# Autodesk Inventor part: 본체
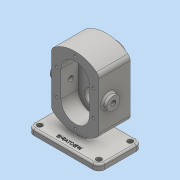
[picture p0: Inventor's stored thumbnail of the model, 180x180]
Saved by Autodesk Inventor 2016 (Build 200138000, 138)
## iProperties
Created: 2019-03
Part Number: 본체
Material: Generic
Document SubType Name: Modeling
Designer: 2-PC10
Density: 1 g/cm^3
Appearance: Default
Author: 2-PC10
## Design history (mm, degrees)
sketch "스케치1"
  geometry: L1 (-60, -36.5)-(60, -36.5); L2 (60, -36.5)-(60, 36.5); L3 (60, 36.5)-(-60, 36.5); L4 (-60, 36.5)-(-60, -36.5); L5 (-60, -36.5)-(60, 36.5); L6 (60, -36.5)-(-60, 36.5); 1 further point
  constraints: 12 end point, 2 midpoint, 2 parallel, 1 horizontal, 1 perpendicular
  dimensions: "d0" = 120 distance of L2.end L3.end; "d1" = 73 distance of L3.end L1.start
extrude "돌출1" new body sketch "스케치1" distance "d2" = 10; taper "d3" = 0 deg
node "작업 평면1"
sketch "스케치2"
  geometry: L1 (120, 10)-(120, 0) reference; L2 (120, 0)-(0, 0) reference; L3 (0, 0)-(0, 10) reference; L4 (0, 10)-(120, 10) reference; L5 (20, 122.721)-(20, 33.279); L6 (100, 122.721)-(100, 33.279); L7 (20, 78)-(100, 78); A1 r 60 centre (60, 78) between (20, 33.279) and (100, 33.279); A2 r 60 centre (60, 78) between (100, 122.721) and (20, 122.721); 2 further points
  constraints: 6 end point, 5 point on circle, 3 midpoint, 2 centre point, 2 vertical, 1 tangent
  dimensions: "d5" = 40 distance from line of point (60, 0) L5; "d6" = 40 distance from line of L6 point (60, 0); "d7" = 78 distance between parallel lines of L2 L7; "d9" = 138 distance of point (60, 0) point (60, 138); "d10" = 60 radius of A2
extrude "돌출2" join sketch "스케치2" distance "d11" = 53; taper "d12" = 0 deg
sketch "스케치3"
  geometry: L1 (120, 10)-(120, 0) reference; L2 (120, 0)-(0, 0) reference; L3 (0, 0)-(0, 10) reference; L4 (0, 10)-(120, 10) reference; L5 (20, 33.279)-(20, 122.721) reference; L6 (100, 122.721)-(100, 33.279) reference; L7 (36, 100)-(36, 56); L8 (84, 100)-(84, 56); A1 r 60 centre (60, 78) between (20, 33.279) and (100, 33.279) reference; A2 r 60 centre (60, 78) between (100, 122.721) and (20, 122.721) reference; A3 r 24 centre (60, 100) between (84, 100) and (36, 100); A4 r 24 centre (60, 56) between (36, 56) and (84, 56); 1 further point
  constraints: 4 end point, 4 point on circle, 2 centre point, 2 tangent, 2 vertical, 1 equal radius
  dimensions: "d13" = 24 distance from line of L7 A1.centre; "d14" = 24 distance from line of L8 A1.centre; "d18" = 24 radius of A3; "d19" = 100 distance from line of L8.start L2; "d20" = 56 distance from line of L8.end L2
extrude "돌출3" cut sketch "스케치3" distance "d21" = 29; taper "d22" = 0 deg
sketch "스케치4"
  geometry: L1 (12.5, 100)-(12.5, 112.5); L2 (12.5, 112.5)-(27.5, 112.5); L3 (27.5, 112.5)-(27.5, 108.5); L4 (27.5, 108.5)-(36.5, 108.5); L5 (36.5, 108.5)-(36.5, 100); L6 (36.5, 100)-(12.5, 100); L7 (-16.5, 138)-(36.5, 138) reference; L8 (36.5, 138)-(36.5, 18) reference; L9 (36.5, 18)-(-16.5, 18) reference; L10 (-16.5, 18)-(-16.5, 32) reference; L11 (-16.5, 32)-(12.5, 32) reference; L12 (12.5, 32)-(12.5, 124) reference; L13 (12.5, 124)-(-16.5, 124) reference; L14 (-16.5, 124)-(-16.5, 138) reference; L15 (-36.5, 0)-(-36.5, 10) reference; L16 (-36.5, 10)-(36.5, 10) reference; L17 (36.5, 10)-(36.5, 0) reference; L18 (36.5, 0)-(-36.5, 0) reference; L19 (-16.5, 100)-(12.5, 100) reference; 1 further point
  constraints: 12 end point, 3 perpendicular, 2 collinear, 2 vertical, 1 parallel, 1 point on line
  dimensions: "d23" = 15 distance between parallel lines of L3 L1; "d24" = 17 diameter of L4 L6; "d25" = 25 diameter of L2 L6
revolve "회전1" sketch "스케치4" stored, may be unused: angle "d26" = 90 deg
sketch "스케치5"
  geometry: L1 (12.5, 56)-(12.5, 68.5); L2 (27.5, 68.5)-(27.5, 56); L3 (27.5, 56)-(12.5, 56); L4 (-16.5, 56)-(12.5, 56) reference; L5 (36.5, 18)-(-16.5, 18) reference; L6 (-16.5, 18)-(-16.5, 32) reference; L7 (-16.5, 32)-(12.5, 32) reference; L8 (12.5, 32)-(12.5, 87.5) reference; L9 (12.5, 87.5)-(27.5, 87.5) reference; L10 (27.5, 87.5)-(27.5, 91.5) reference; L11 (27.5, 91.5)-(36.5, 91.5) reference; L12 (36.5, 91.5)-(36.5, 18) reference; L13 (-16.5, 138)-(36.5, 138) reference; L14 (36.5, 138)-(36.5, 108.5) reference; L15 (36.5, 108.5)-(27.5, 108.5) reference; L16 (27.5, 108.5)-(27.5, 112.5) reference; L17 (27.5, 112.5)-(12.5, 112.5) reference; L18 (12.5, 112.5)-(12.5, 124) reference; L19 (12.5, 124)-(-16.5, 124) reference; L20 (-16.5, 124)-(-16.5, 138) reference; L21 (-36.5, 0)-(-36.5, 10) reference; L22 (-36.5, 10)-(36.5, 10) reference; L23 (36.5, 10)-(36.5, 0) reference; L24 (36.5, 0)-(-36.5, 0) reference; L25 (12.5, 68.5)-(27.5, 68.5); 1 further point
  constraints: 8 end point, 1 collinear, 1 horizontal, 1 perpendicular, 1 point on line, 1 vertical
  dimensions: "d29" = 15 distance between parallel lines of L2 L1; "d30" = 25 diameter of L25 L3
revolve "회전2" sketch "스케치5" stored, may be unused: angle "d31" = 90 deg
node "작업 평면2"
sketch "스케치7"
  geometry: L1 (-60, 0)-(60, 0) reference; C1 r 19 at (0, 100); 2 further points
  constraints: 1 centre point, 1 midpoint, 1 vertical alignment
  dimensions: "d36" = 38 diameter of C1; "d37" = 100 distance of point (0, 0) C1.centre
extrude "돌출5" join sketch "스케치7" distance "d38" = 17; taper "d39" = 0 deg
hole "구멍1" diameter "d42" = 28; stored, may be unused: countersink angle "d46" = 90 deg, drill point angle "d48" = 0 deg; dims "d43" = 6, "d44" = 4, "d45" = 2, "d47" = 7.3, "d49" = 10, "d50" = 10
hole "구멍2" diameter "d53" = 17; stored, may be unused: countersink angle "d57" = 90 deg, drill point angle "d59" = 118 deg; dims "d51" = 10, "d52" = 10, "d54" = 6, "d55" = 4, "d56" = 2, "d58" = 7.3
sketch "스케치8"
  geometry: L1 (122.721, -20)-(122.721, 53) reference; L2 (0, 0)-(0, 53) reference; L3 (0, 53)-(89.443, 53) reference; L4 (89.443, 53)-(89.443, 0) reference; L5 (89.443, 0)-(0, 0) reference; L6 (122.721, -20)-(112.721, -20) reference; L7 (112.721, -20)-(112.721, 53) reference; L8 (112.721, 53)-(122.721, 53) reference; L9 (122.721, 53)-(122.721, -20) reference; C1 r 11 at (44.721, 16.5); 3 further points
  constraints: 2 midpoint, 1 centre point, 1 horizontal alignment, 1 vertical alignment
  dimensions: "d60" = 22 diameter of C1
extrude "돌출6" join sketch "스케치8" distance "d61" = 8; taper "d62" = 0 deg
fillet "모깎기1" dims "d63" = 10
hole "구멍3" diameter "d66" = 9; stored, may be unused: countersink angle "d70" = 90 deg, drill point angle "d72" = 118 deg; dims "d64" = 10, "d65" = 10, "d67" = 6, "d68" = 4, "d69" = 2, "d71" = 7.3
hole "구멍4" diameter "d75" = 9; stored, may be unused: countersink angle "d79" = 90 deg, drill point angle "d81" = 118 deg; dims "d73" = 10, "d74" = 10, "d76" = 6, "d77" = 4, "d78" = 2, "d80" = 7.3
hole "구멍5" diameter "d84" = 9; stored, may be unused: countersink angle "d88" = 90 deg, drill point angle "d90" = 118 deg; dims "d82" = 10, "d83" = 10, "d85" = 6, "d86" = 4, "d87" = 2, "d89" = 7.3
hole "구멍6" diameter "d93" = 9; stored, may be unused: countersink angle "d97" = 90 deg, drill point angle "d99" = 118 deg; dims "d91" = 10, "d92" = 10, "d94" = 6, "d95" = 4, "d96" = 2, "d98" = 7.3
sketch "스케치9"
  geometry: L1 (-25, -22.5)-(25, -22.5); L2 (25, -22.5)-(25, -30.5); L3 (25, -30.5)-(-25, -30.5); L4 (-25, -30.5)-(-25, -22.5); L5 (-25, -26.5)-(25, -26.5); L6 (0, -22.5)-(0, -30.5); L7 (-60, 26.5)-(-60, -26.5) reference; L8 (-50, -36.5)-(50, -36.5) reference; 1 further point
  constraints: 4 end point, 4 midpoint, 2 other
  dimensions: "d100" = 8 distance of L6.start L6.end; "d101" = 50 distance of L5.start L5.end; "d102" = 60 distance between parallel lines of L6 L7; "d103" = 10 distance between parallel lines of L5 L8
feature "엠보싱1" sketch "스케치9" dims "d104" = 0.5, "d105" = 0
sketch "스케치10"
  geometry: L1 (-6, -6.5)-(6, -6.5); L2 (6, -6.5)-(6, 36.5); L3 (6, 36.5)-(-6, 36.5); L4 (-6, 36.5)-(-6, -6.5); L5 (18.989, -26.503)-(17.659, -26.503) reference; L6 (17.659, -26.503)-(17.659, -26.123) reference; L7 (17.659, -26.123)-(18.989, -26.123) reference; L8 (18.989, -26.123)-(18.989, -23.545) reference; L9 (18.989, -23.545)-(19.315, -23.545) reference; L10 (19.45, -23.81)-(19.45, -29.482) reference; L11 (19.45, -29.482)-(18.989, -29.482) reference; L12 (18.989, -29.482)-(18.989, -26.503) reference; L13 (-13.942, -25.852)-(-13.942, -26.246) reference; L14 (-13.942, -26.246)-(-15.061, -26.246) reference; L15 (-15.061, -26.246)-(-15.061, -27.989) reference; L16 (-15.061, -27.989)-(-15.536, -27.989) reference; L17 (-15.536, -27.989)-(-15.536, -23.498) reference; L18 (-15.536, -23.498)-(-15.231, -23.498) reference; L19 (-15.061, -23.763)-(-15.061, -25.852) reference; L20 (-15.061, -25.852)-(-13.942, -25.852) reference; L21 (-14.844, -28.939)-(-14.844, -29.319) reference; L22 (-14.844, -29.319)-(-19.193, -29.319) reference; L23 (-19.193, -29.319)-(-19.193, -27.691) reference; L24 (-19.193, -27.691)-(-18.84, -27.691) reference; L25 (-18.731, -27.908)-(-18.731, -28.939) reference; L26 (-18.731, -28.939)-(-14.844, -28.939) reference; L27 (-17.374, -24.075)-(-18.853, -24.075) reference; L28 (-18.853, -24.075)-(-18.853, -23.722) reference; L29 (-18.853, -23.722)-(-17.374, -23.722) reference; L30 (-17.374, -23.722)-(-17.374, -24.075) reference; L31 (-20.047, -24.882)-(-20.047, -24.529) reference; L32 (-20.047, -24.529)-(-16.282, -24.529) reference; L33 (-16.282, -24.529)-(-16.282, -24.882) reference; L34 (-16.282, -24.882)-(-20.047, -24.882) reference; L35 (-2.917, -29.115)-(-3.474, -27.589) reference; L36 (-3.474, -27.589)-(-5.726, -27.589) reference; L37 (-5.726, -27.589)-(-6.296, -29.115) reference; L38 (-6.296, -29.115)-(-6.777, -29.115) reference; L39 (-6.777, -29.115)-(-4.878, -24.115) reference; L40 (-4.878, -24.115)-(-4.335, -24.115) reference; L41 (-4.335, -24.115)-(-2.436, -29.115) reference; L42 (-2.436, -29.115)-(-2.917, -29.115) reference; L43 (-4.613, -24.604)-(-5.57, -27.175) reference; L44 (-5.57, -27.175)-(-3.636, -27.175) reference; L45 (-3.636, -27.175)-(-4.613, -24.604) reference; L46 (-10.095, -27.351)-(-8.284, -27.351) reference; L47 (-8.284, -27.351)-(-8.284, -29.475) reference; L48 (-8.284, -29.475)-(-8.745, -29.475) reference; L49 (-8.745, -29.475)-(-8.745, -27.725) reference; L50 (-8.745, -27.725)-(-12.578, -27.725) reference; L51 (-12.578, -27.725)-(-12.578, -27.351) reference; L52 (-12.578, -27.351)-(-10.55, -27.351) reference; L53 (-10.55, -27.351)-(-10.55, -26.13) reference; L54 (-10.55, -26.13)-(-13.311, -26.13) reference; L55 (-13.311, -26.13)-(-13.311, -25.757) reference; L56 (-13.311, -25.757)-(-8.942, -25.757) reference; L57 (-8.657, -24.088)-(-12.463, -24.088) reference; L58 (-12.463, -24.088)-(-12.463, -23.708) reference; L59 (-12.463, -23.708)-(-8.175, -23.708) reference; L60 (-8.446, -25.757)-(-7.307, -25.757) reference; L61 (-7.307, -25.757)-(-7.307, -26.13) reference; L62 (-7.307, -26.13)-(-10.095, -26.13) reference; L63 (-10.095, -26.13)-(-10.095, -27.351) reference; L64 (1.526, -24.115)-(1.526, -24.529) reference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; C1 r 4.5 at (-50, 26.5) reference; C2 r 4.5 at (50, 26.5) reference; C3 r 4.5 at (50, -26.5) reference; C4 r 4.5 at (-50, -26.5) reference; A1 r 10 centre (-50, 26.5) between (-50, 36.5) and (-60, 26.5) reference; A2 r 10 centre (50, 26.5) between (60, 26.5) and (50, 36.5) reference; A3 r 10 centre (50, -26.5) between (50, -36.5) and (60, -26.5) reference; A4 r 10 centre (-50, -26.5) between (-60, -26.5) and (-50, -36.5) reference; 62 further points
  constraints: 8 end point, 2 parallel, 1 collinear, 1 horizontal, 1 perpendicular, 76 other
  dimensions: "d106" = 43 distance of L3.end L1.start; "d107" = 6 distance from line of L4 point (0, 0); "d108" = 6 distance from line of point (0, 0) L2
extrude "돌출7" join sketch "스케치10" stored distance "d109" = 0; taper "d110" = 0 deg
sketch "스케치11"
  geometry: L1 (29, 100)-(29, 56); L2 (91, 100)-(91, 56); L3 (36, 100)-(36, 56) reference; L4 (84, 56)-(84, 100) reference; L5 (20, 33.279)-(20, 122.721) reference; L6 (100, 122.721)-(100, 33.279) reference; L7 (0, 10)-(120, 10) reference; L8 (120, 10)-(120, 0) reference; L9 (120, 0)-(0, 0) reference; L10 (0, 0)-(0, 10) reference; L11 (10, 0)-(110, 0) reference; A1 r 24 centre (60, 100) between (84, 100) and (36, 100) reference; A2 r 24 centre (60, 56) between (36, 56) and (84, 56) reference; A3 r 60 centre (60, 78) between (20, 33.279) and (100, 33.279) reference; A4 r 60 centre (60, 78) between (100, 122.721) and (20, 122.721) reference; A5 r 31 centre (60, 100) between (91, 100) and (29, 100); A6 r 31 centre (60, 56) between (29, 56) and (91, 56); 9 further points
  constraints: 6 coincident, 6 point on circle, 4 end point, 3 tangent, 2 centre point, 2 midpoint, 2 vertical, 2 vertical alignment
  dimensions: "d112" = 31 radius of A5
hole "구멍7" sketch "스케치11" at (60, 131), (60, 25), (29, 100), (91, 100), (91, 56), (29, 56) diameter "d113" = 4.134; stored, may be unused: countersink angle "d117" = 90 deg, drill point angle "d119" = 118 deg; dims "d114" = 10, "d115" = 4, "d116" = 2, "d118" = 12
hole "구멍8" diameter "d122" = 8.376; stored, may be unused: countersink angle "d126" = 90 deg, drill point angle "d128" = 118 deg; dims "d120" = 10, "d121" = 10, "d123" = 20, "d124" = 4, "d125" = 2, "d127" = 27.3
chamfer "모따기1" distance "d129" = 1; stored, may be unused: second distance "d130" = 2, angle "d131" = 45 deg
fillet "모깎기2" dims "d138" = 3
fillet "모깎기3" dims "d139" = 3
fillet "모깎기4" dims "d140" = 3
fillet "모깎기5" dims "d141" = 3
fillet "모깎기6" dims "d142" = 0.5
chamfer "모따기4" distance "d143" = 0.7; stored, may be unused: second distance "d144" = 2, angle "d145" = 30 deg
fillet "모깎기7" dims "d146" = 10
fillet "모깎기8" dims "d147" = 3
fillet "모깎기9" dims "d148" = 3
fillet "모깎기10" dims "d149" = 3
node "솔리드1"
mirror "대칭1"
mirror "대칭2"
node "절단 모서리 투영1"
node "절단 모서리 투영2"
node "절단 모서리 투영3"
node "절단 모서리 투영4"
node "절단 모서리 투영6"
node "절단 모서리 투영7"
node "절단 모서리 투영8"
other parameters: "d35" = 36.5, "d111" = 62
